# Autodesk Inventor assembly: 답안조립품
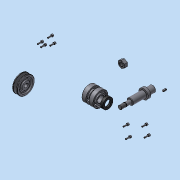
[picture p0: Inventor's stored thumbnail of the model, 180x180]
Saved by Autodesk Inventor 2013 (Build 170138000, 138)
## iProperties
Created: 2015-03
Part Number: 답안조립품
Document SubType Name: Assembly
Designer: dgall
Author: dgall
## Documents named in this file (11)
- C:\Users\dgall\Desktop\450305V1037\답안조립품.iam
- C:\Users\dgall\Desktop\450305V1037\본체.ipt
- C:\Users\dgall\Desktop\450305V1037\축.ipt
- C:\Users\dgall\Desktop\450305V1037\V벨트풀리.ipt
- C:\Users\dgall\Desktop\450305V1037\커버.ipt
- C:\Users\dgall\Desktop\450305V1037\커버2.ipt
- C:\Users\dgall\Desktop\450305V1037\베어링 6204.ipt
- C:\Users\dgall\Desktop\450305V1037\오일실.ipt
- C:\Users\dgall\Desktop\450305V1037\키(4 x 4 x 12).ipt
- C:\Users\dgall\Desktop\450305V1037\너트 M12x1.25.ipt
- C:\Users\dgall\Desktop\450305V1037\M 4 x 12.ipt
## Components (14 placed, 6 different names)
1. 그루브 풀리1:1
2. KS B 2023 6204 - 20 x 47 x 14:1
3. KS B 2023 6204 - 20 x 47 x 14:2
4. KS B 2804 D D - 20 32 8:1
5. KS B 1311 (I) 4 x 4 x 12:1
6. KS B 1012 클래스 1 일반 - 미터 M12x1.25:1
7. KS B 1003 - 미터 M 4 x 12:1
8. KS B 1003 - 미터 M 4 x 12:2
9. KS B 1003 - 미터 M 4 x 12:3
10. KS B 1003 - 미터 M 4 x 12:4
11. KS B 1003 - 미터 M 4 x 12:5
12. KS B 1003 - 미터 M 4 x 12:6
13. KS B 1003 - 미터 M 4 x 12:7
14. KS B 1003 - 미터 M 4 x 12:8
